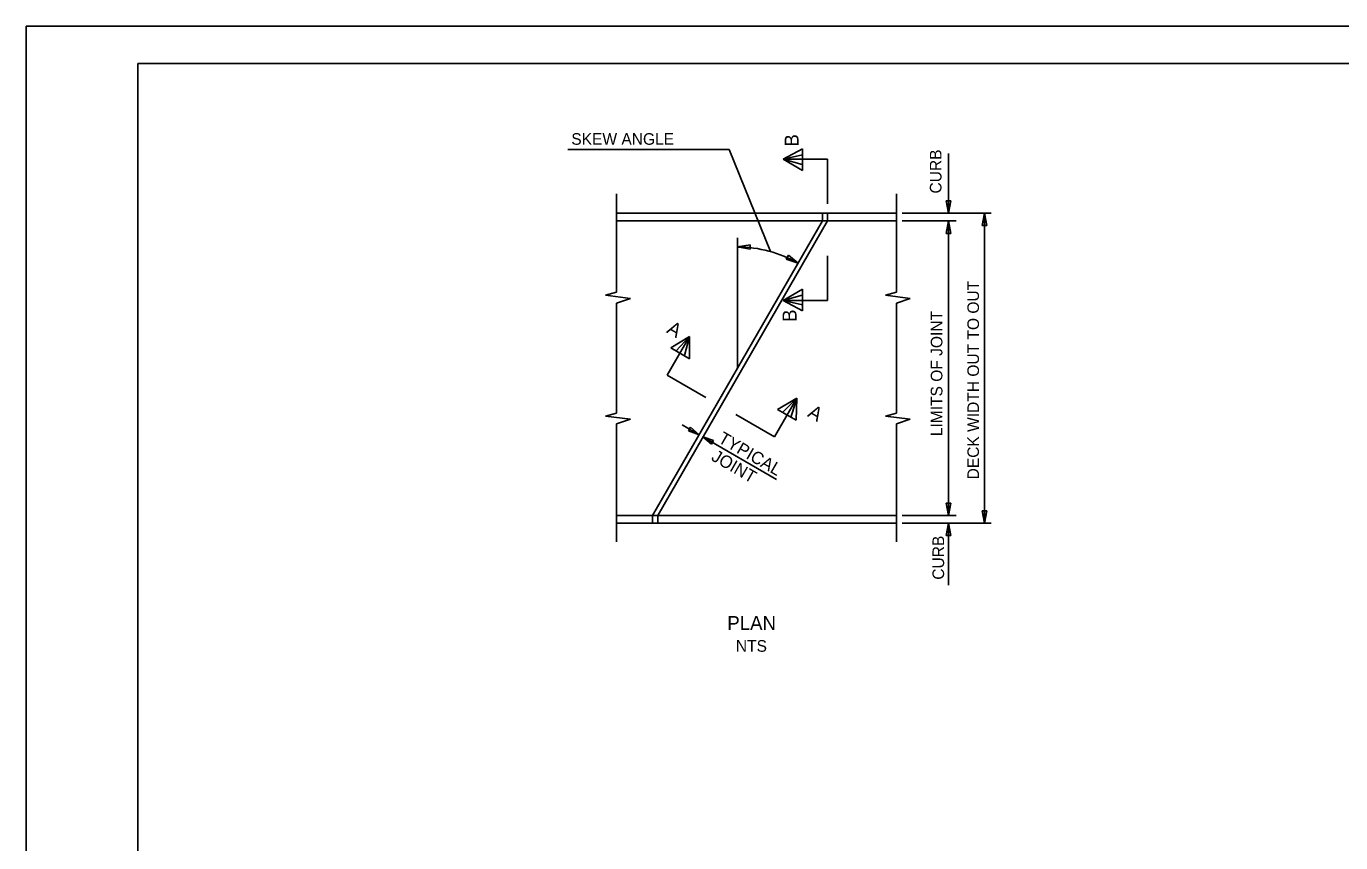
# Model space of a CAD drawing. Extents: x 0 to 11.3, y 0 to 7.8.
# Drawn here: x 0 to 5.89, y 3.68 to 7.33 of the extents above; entities that cross this region are included whole.
import ezdxf

# ---------------------------------------------------------------- set-up
doc = ezdxf.new("R2010")
doc.units = 0
for name, color, linetype in [('BORDER_ANNO_Cutsheet', 7, 'Continuous'), ('BRDG_ANNO_Anno-Sheet', 7, 'Continuous'), ('BRDG_ANNO_General-Notes', 7, 'Continuous'), ('BRDG_BASE_Obj-Line', 7, 'Continuous')]:
    doc.layers.add(name, color=color, linetype=linetype)

msp = doc.modelspace()

# ---------------------------------------------------------------- linework, layer by layer
at = {"layer": 'BORDER_ANNO_Cutsheet'}
msp.add_lwpolyline([(0, 7.3333), (11.3333, 7.3333), (11.3333, 0), (0, 0)], close=True, dxfattribs=at)
at = {"layer": 'BRDG_ANNO_Anno-Sheet'}
msp.add_lwpolyline([(0.5, 7.1667), (11.1667, 7.1667), (11.1667, 0.1667), (0.5, 0.1667)], close=True, dxfattribs=at)
at = {"layer": 'BRDG_ANNO_General-Notes'}
for p, q in [((2.4269, 6.7819), (3.1495, 6.7819)), ((3.1495, 6.7819), (3.3349, 6.324)), ((3.3908, 6.7376), (3.4774, 6.7845)), ((3.4774, 6.7845), (3.4774, 6.6876)), ((3.3908, 6.7376), (3.4779, 6.7577)), ((3.5908, 6.7376), (3.3908, 6.7376)), ((3.3908, 6.7376), (3.4774, 6.6876)), ((3.3908, 6.7376), (3.4761, 6.7144)), ((3.5908, 6.7376), (3.5908, 6.5376)), ((4.1318, 6.7639), (4.1318, 6.4958)), ((4.1422, 6.5514), (4.1214, 6.5514)), ((4.1214, 6.5514), (4.1318, 6.4958)), ((4.1318, 6.4958), (4.1422, 6.5514)), ((3.9252, 6.4958), (4.3238, 6.4958)), ((4.2936, 6.4958), (4.2832, 6.4403)), ((4.2936, 5.1069), (4.2936, 6.4958)), ((4.304, 6.4403), (4.2936, 6.4958)), ((3.9252, 6.4611), (4.1665, 6.4611)), ((4.1318, 6.4611), (4.1214, 6.4055)), ((4.1318, 5.1417), (4.1318, 6.4611)), ((4.1422, 6.4055), (4.1318, 6.4611)), ((4.2832, 6.4403), (4.304, 6.4403)), ((3.1873, 5.8014), (3.1873, 6.3857)), ((4.1214, 6.4055), (4.1422, 6.4055)), ((3.2429, 6.3548), (3.1873, 6.3444)), ((3.1873, 6.3444), (3.2429, 6.334)), ((3.2429, 6.334), (3.2429, 6.3548)), ((3.4158, 6.3083), (3.4054, 6.2903)), ((3.4589, 6.2715), (3.4158, 6.3083)), ((3.5908, 6.1052), (3.5908, 6.3052)), ((3.4054, 6.2903), (3.4589, 6.2715)), ((3.3908, 6.1052), (3.4774, 6.1552)), ((3.3908, 6.1052), (3.4761, 6.1284)), ((3.4774, 6.0583), (3.4774, 6.1552)), ((3.5908, 6.1052), (3.3908, 6.1052)), ((3.3908, 6.1052), (3.4774, 6.0583)), ((3.3908, 6.1052), (3.4779, 6.0851)), ((2.8721, 5.7704), (2.9721, 5.9436)), ((2.9721, 5.9436), (2.8881, 5.892)), ((2.8881, 5.892), (2.9721, 5.8436)), ((2.9721, 5.9436), (2.9111, 5.8782)), ((2.9721, 5.9436), (2.9495, 5.8582)), ((2.9721, 5.9436), (2.9721, 5.8436)), ((2.8721, 5.7704), (3.0453, 5.6704)), ((3.3523, 5.4932), (3.4523, 5.6665)), ((3.4523, 5.6665), (3.3657, 5.6165)), ((3.4523, 5.6665), (3.3897, 5.6042)), ((3.4523, 5.6665), (3.4263, 5.5809)), ((3.4523, 5.6665), (3.4497, 5.568)), ((3.4497, 5.568), (3.3657, 5.6165)), ((2.9387, 5.5474), (3.0151, 5.5033)), ((2.9671, 5.5202), (2.9765, 5.5365)), ((2.9765, 5.5365), (3.0151, 5.5033)), ((3.3523, 5.4932), (3.1791, 5.5931)), ((3.0151, 5.5033), (2.9671, 5.5202)), ((3.0314, 5.4938), (3.361, 5.303)), ((3.0699, 5.4606), (3.0314, 5.4938)), ((3.0314, 5.4938), (3.0793, 5.4769)), ((3.0793, 5.4769), (3.0699, 5.4606)), ((4.1422, 5.1972), (4.1214, 5.1972)), ((4.1214, 5.1972), (4.1318, 5.1417)), ((4.1318, 5.1417), (4.1422, 5.1972)), ((3.9252, 5.1417), (4.1665, 5.1417)), ((4.304, 5.1625), (4.2832, 5.1625)), ((4.2832, 5.1625), (4.2936, 5.1069)), ((4.2936, 5.1069), (4.304, 5.1625)), ((3.9252, 5.1069), (4.3238, 5.1069)), ((4.1318, 5.1069), (4.1214, 5.0514)), ((4.1318, 4.8295), (4.1318, 5.1069)), ((4.1422, 5.0514), (4.1318, 5.1069)), ((4.1214, 5.0514), (4.1422, 5.0514))]:
    msp.add_line(p, q, dxfattribs=at)
msp.add_arc((3.1873, 5.8014), 0.5429, 59.9915, 90, dxfattribs=at)
at = {"layer": 'BRDG_BASE_Obj-Line'}
for p, q in [((2.6443, 6.583), (2.6443, 6.1417)), ((3.8988, 6.583), (3.8988, 6.1417)), ((3.8988, 6.4958), (2.6443, 6.4958)), ((3.5682, 6.4611), (3.5682, 6.4958)), ((3.5908, 6.4611), (3.5908, 6.4958)), ((3.8988, 6.4611), (2.6443, 6.4611)), ((2.8065, 5.1417), (3.5682, 6.4611)), ((2.8294, 5.1417), (3.5908, 6.4611)), ((2.5957, 6.1278), (2.6443, 6.1417)), ((2.7068, 6.1139), (2.5957, 6.1278)), ((3.8502, 6.1278), (3.8988, 6.1417)), ((3.9613, 6.1139), (3.8502, 6.1278)), ((2.6443, 6.093), (2.7068, 6.1139)), ((2.6443, 6.093), (2.6443, 5.6)), ((3.8988, 6.093), (3.9613, 6.1139)), ((3.8988, 6.093), (3.8988, 5.6)), ((2.5957, 5.5861), (2.6443, 5.6)), ((3.8502, 5.5861), (3.8988, 5.6)), ((2.7068, 5.5722), (2.5957, 5.5861)), ((2.6443, 5.5514), (2.7068, 5.5722)), ((2.6443, 5.5514), (2.6443, 5.0236)), ((3.9613, 5.5722), (3.8502, 5.5861)), ((3.8988, 5.5514), (3.9613, 5.5722)), ((3.8988, 5.5514), (3.8988, 5.0236)), ((3.8988, 5.1417), (2.6443, 5.1417)), ((2.8065, 5.1069), (2.8065, 5.1417)), ((2.8294, 5.1069), (2.8294, 5.1417)), ((3.8988, 5.1069), (2.6443, 5.1069))]:
    msp.add_line(p, q, dxfattribs=at)

# ---------------------------------------------------------------- texts
at = {"layer": 'BRDG_ANNO_General-Notes'}
for s, height, p in [('SKEW ANGLE', 0.05208, (2.4422, 6.8024)), ('PLAN', 0.0625, (3.141, 4.6282)), ('NTS', 0.05208, (3.1796, 4.5307))]:
    msp.add_text(s, height=height, dxfattribs=at).set_placement(p)
for s, height, rotation, p in [('B', 0.0625, 90, (3.4607, 6.7942)), ('CURB', 0.05208, 90, (4.1009, 6.584)), ('DECK WIDTH OUT TO OUT', 0.052083, 90, (4.269, 5.3029)), ('B', 0.0625, 90, (3.4516, 6.0088)), ('LIMITS OF JOINT', 0.052083, 90, (4.1051, 5.4967)), ('A', 0.0625, 330, (2.8652, 5.9629)), ('A', 0.0625, 330, (3.4966, 5.5872)), ('TYPICAL', 0.05556, 330, (3.096, 5.4716)), ('JOINT', 0.05556, 330, (3.0652, 5.3912)), ('CURB', 0.05208, 90, (4.1127, 4.8535))]:
    msp.add_text(s, height=height, rotation=rotation, dxfattribs=at).set_placement(p)

doc.saveas('drawing.dxf')
